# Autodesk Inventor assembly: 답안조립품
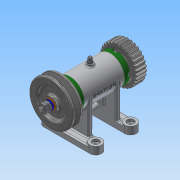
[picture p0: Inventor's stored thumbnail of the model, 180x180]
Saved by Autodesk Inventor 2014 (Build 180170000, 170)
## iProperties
Created: 2015-11
Part Number: 답안조립품
Document SubType Name: Assembly
Designer: 103-30
Author: 103-30
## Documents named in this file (16)
- C:\Users\103-30\Desktop\451110V1032\답안조립품.iam
- C:\Users\103-30\Desktop\451110V1032\1-본체.ipt
- C:\Users\103-30\Desktop\451110V1032\축.ipt
- C:\Users\103-30\Desktop\451110V1032\베어링 15 x 32 x 9.ipt
- C:\Users\103-30\Desktop\451110V1032\키 3 x 3 x 12.ipt
- C:\Users\103-30\Desktop\451110V1032\커버.ipt
- C:\Users\103-30\Desktop\451110V1032\오일 실 15 25 7.ipt
- C:\Users\103-30\Desktop\451110V1032\니플 M 6 x 0.75.ipt
- C:\Users\103-30\Desktop\451110V1032\스퍼기어.ipt
- C:\Users\103-30\Desktop\451110V1032\와셔 8x17.ipt
- C:\Users\103-30\Desktop\451110V1032\스프링와셔 8.ipt
- C:\Users\103-30\Desktop\451110V1032\너트 M 8.ipt
- C:\Users\103-30\Desktop\451110V1032\V벨트풀리.ipt
- C:\Users\103-30\Desktop\451110V1032\와셔 6x11.5.ipt
- C:\Users\103-30\Desktop\451110V1032\볼트 M 6 x 8.ipt
- C:\Users\103-30\Desktop\451110V1032\볼트 M4 x 12.ipt
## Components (12 placed, 4 different names)
1. 1-본체:1
2. KS B 2023 6002 - 15 x 32 x 9:1
3. KS B 2023 6002 - 15 x 32 x 9:2
4. V벨트풀리:1 — 각도:4
5. ISO 4762 M4 x 12:1
6. ISO 4762 M4 x 12:3
7. ISO 4762 M4 x 12:4
8. ISO 4762 M4 x 12:5
9. ISO 4762 M4 x 12:2
10. ISO 4762 M4 x 12:6
11. ISO 4762 M4 x 12:7
12. ISO 4762 M4 x 12:8
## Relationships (1: Angle 1)
- 각도:4 [Angle]: V벨트풀리:1
## Named parameters: d12_d10 = 0, d13_d11 = 0
